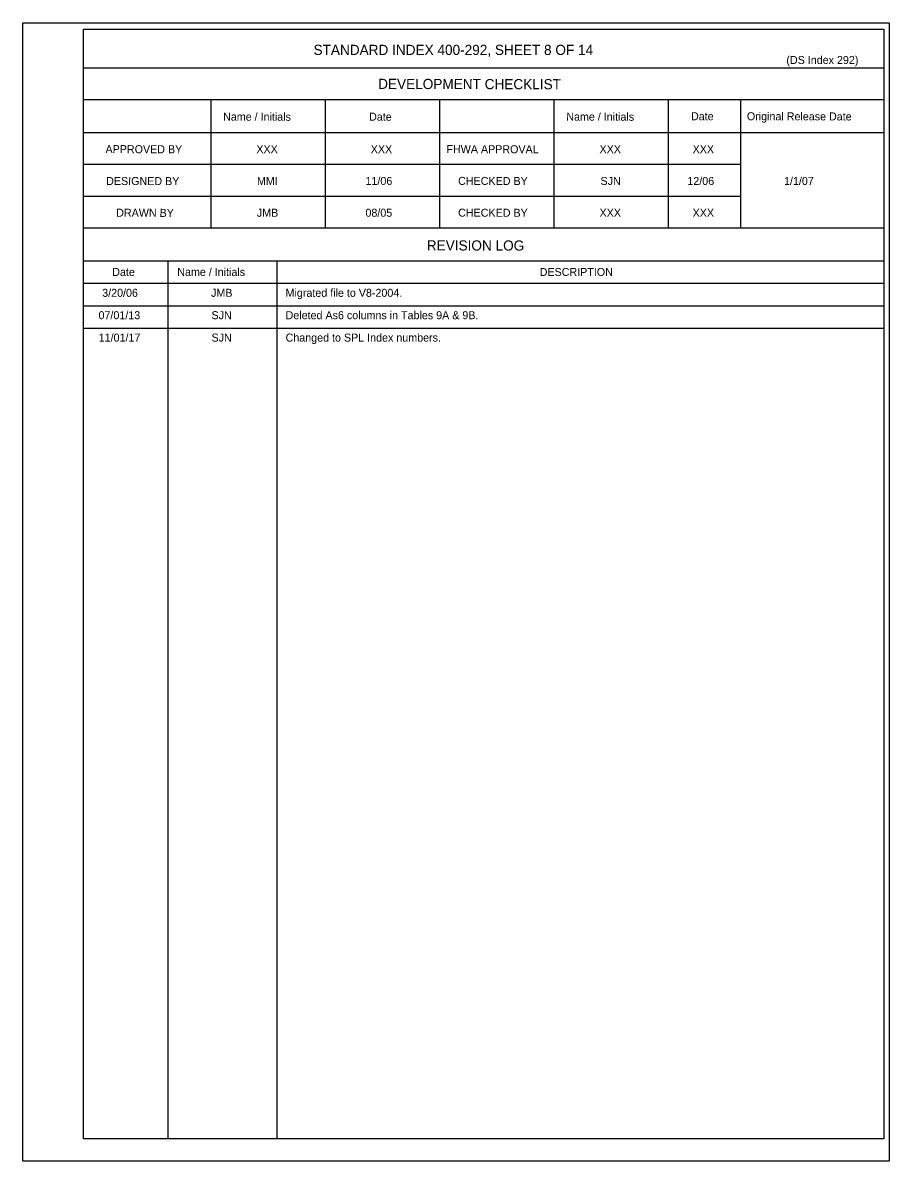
# Model space of a CAD drawing. Extents: x 10338.56 to 10340.78, y 76371.51 to 76372.62.
# Drawn here: x 10340.094 to 10340.775, y 76371.667 to 76372.563 of the extents above; entities that cross this region are included whole.
import ezdxf

# ---------------------------------------------------------------- set-up
doc = ezdxf.new("R2010")
doc.units = 0
for name, color, linetype in [('Border', 7, 'Continuous'), ('SheetBorder_dp', 7, 'Continuous'), ('TextMisc', 7, 'Continuous')]:
    doc.layers.add(name, color=color, linetype=linetype)

msp = doc.modelspace()

# ---------------------------------------------------------------- linework, layer by layer
at = {"layer": 'Border'}
for p, q in [((10340.77101, 76372.52706), (10340.14142, 76372.52706)), ((10340.77101, 76372.50206), (10340.14142, 76372.50206)), ((10340.24142, 76372.50206), (10340.24142, 76372.40119)), ((10340.33142, 76372.50206), (10340.33142, 76372.40119)), ((10340.42142, 76372.50206), (10340.42142, 76372.40119)), ((10340.51142, 76372.50206), (10340.51142, 76372.40119)), ((10340.60142, 76372.50206), (10340.60142, 76372.40119)), ((10340.65814, 76372.50206), (10340.65814, 76372.40119)), ((10340.77101, 76372.47619), (10340.14142, 76372.47619)), ((10340.65814, 76372.45119), (10340.14142, 76372.45119)), ((10340.65814, 76372.42619), (10340.14142, 76372.42619)), ((10340.77101, 76372.40119), (10340.14142, 76372.40119)), ((10340.77101, 76372.37532), (10340.14142, 76372.37532)), ((10340.20768, 76372.37532), (10340.20768, 76371.68449)), ((10340.29338, 76372.37532), (10340.29338, 76371.68449)), ((10340.77101, 76372.3577), (10340.14142, 76372.3577))]:
    msp.add_line(p, q, dxfattribs=at)
msp.add_lwpolyline([(10340.14143, 76372.5577), (10340.77101, 76372.5577), (10340.77101, 76371.68449), (10340.14143, 76371.68449)], close=True, dxfattribs=at)
at = {"layer": 'SheetBorder_dp'}
for p, q in [((10340.14142, 76372.34008), (10340.77101, 76372.34008)), ((10340.14142, 76372.32247), (10340.77101, 76372.32247))]:
    msp.add_line(p, q, dxfattribs=at)
at = {"layer": 'TextMisc'}
msp.add_line((10340.0936, 76371.66695), (10340.0936, 76371.66695), dxfattribs=at)
msp.add_lwpolyline([(10340.0936, 76372.56278), (10340.77526, 76372.56278), (10340.77526, 76371.66695), (10340.0936, 76371.66695)], close=True, dxfattribs=at)

# ---------------------------------------------------------------- texts
at = {"layer": 'SheetBorder_dp'}
for s, height, p in [('STANDARD INDEX 400-292, SHEET 8 OF 14', 0.008, (10340.32235, 76372.53745)), ('(DS Index 292)', 0.0063, (10340.69435, 76372.53035)), ('XXX', 0.0063, (10340.27736, 76372.46015)), ('XXX', 0.0063, (10340.36736, 76372.46015)), ('XXX', 0.0063, (10340.54736, 76372.46015)), ('XXX', 0.0063, (10340.62059, 76372.46015)), ('MMI', 0.0063, (10340.27785, 76372.43515)), ('11/06', 0.0063, (10340.36322, 76372.43515)), ('SJN', 0.0063, (10340.54812, 76372.43515)), ('12/06', 0.0063, (10340.61645, 76372.43515)), ('1/1/07', 0.0063, (10340.69251, 76372.43515)), ('JMB', 0.0063, (10340.27777, 76372.41015)), ('08/05', 0.0063, (10340.36318, 76372.41015)), ('XXX', 0.0063, (10340.54736, 76372.41015)), ('XXX', 0.0063, (10340.62059, 76372.41015)), ('DESCRIPTION', 0.0063, (10340.50028, 76372.36354)), ('3/20/06', 0.0063, (10340.15609, 76372.34714)), ('JMB', 0.0063, (10340.24173, 76372.34714)), ('Migrated file to V8-2004.', 0.0063, (10340.30036, 76372.34714)), ('07/01/13', 0.0063, (10340.15319, 76372.32952)), ('SJN', 0.0063, (10340.24209, 76372.32952)), ('Deleted As6 columns in Tables 9A & 9B.', 0.0063, (10340.30036, 76372.32952)), ('11/01/17', 0.0063, (10340.15333, 76372.3119)), ('SJN', 0.0063, (10340.24209, 76372.3119)), ('Changed to SPL Index numbers.', 0.0063, (10340.30036, 76372.3119))]:
    msp.add_text(s, height=height, dxfattribs=at).set_placement(p)
for s, height, p in [('DEVELOPMENT CHECKLIST', 0.008, (10340.37317, 76372.51071)), ('Name / Initials', 0.0063, (10340.25119, 76372.48578)), ('Date', 0.0063, (10340.36602, 76372.48573)), ('Name / Initials', 0.0063, (10340.52119, 76372.48578)), ('Date', 0.0063, (10340.6193, 76372.48609)), ('Original Release Date', 0.0063, (10340.66326, 76372.48608)), ('APPROVED BY', 0.0063, (10340.15866, 76372.46021)), ('FHWA APPROVAL', 0.0063, (10340.42689, 76372.46021)), ('DESIGNED BY', 0.0063, (10340.15919, 76372.43515)), ('CHECKED BY', 0.0063, (10340.43611, 76372.43521)), ('DRAWN BY', 0.0063, (10340.16709, 76372.41015)), ('CHECKED BY', 0.0063, (10340.43611, 76372.41021)), ('REVISION LOG', 0.008, (10340.41145, 76372.38365)), ('Date', 0.0063, (10340.16399, 76372.36356)), ('Name / Initials', 0.0063, (10340.21514, 76372.36361))]:
    msp.add_text(s, height=height, rotation=359.87563, dxfattribs=at).set_placement(p)

doc.saveas('drawing.dxf')
